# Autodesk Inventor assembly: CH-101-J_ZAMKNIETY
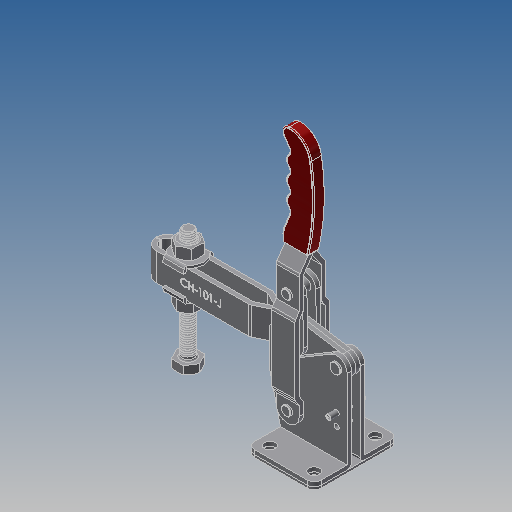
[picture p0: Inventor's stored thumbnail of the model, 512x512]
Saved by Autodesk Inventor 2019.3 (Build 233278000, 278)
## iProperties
Company: Î¢ÈíÖÐ¹ú
Created: 2012-09
Part Number: CH-101-J_ZAMKNIETY
Material: Ogólny
Description: STEP AP203
Document SubType Name: Assembly
Designer: CADENGINEERING4
Sending System: SolidWorks 2010
Preprocessor: SwSTEP 2.0
Title: CH-101-J.STEP
Author: Î¢ÈíÓÃ»§
Revision Number: ÈÎºÎ
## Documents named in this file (16)
- E:\STRONA\Piotrek\CH-101-J\CH-101-J_ZAMKNIETY.iam
- E:\STRONA\Piotrek\CH-101-J\CH-101-J-02 U-BAR.ipt
- E:\STRONA\Piotrek\CH-101-J\CH-101-J-01 FLANGED BASE.ipt
- E:\STRONA\Piotrek\CH-101-J\CH-FW-580.ipt
- E:\STRONA\Piotrek\CH-101-J\CH-101-J-06.ipt
- E:\STRONA\Piotrek\CH-101-J\CH-101-J-03 HANDLE.ipt
- E:\STRONA\Piotrek\CH-101-J\CH-SA-58500 SPINDLE SUPPLIED.ipt
- E:\STRONA\Piotrek\CH-101-J\CH-101-J-11.ipt
- E:\STRONA\Piotrek\CH-101-J\CH-10247-08.ipt
- E:\STRONA\Piotrek\CH-101-J\CH-101-J-07.ipt
- E:\STRONA\Piotrek\CH-101-J\CH-10247-05.ipt
- E:\STRONA\Piotrek\CH-101-J\CH-101-J-05.ipt
- E:\STRONA\Piotrek\CH-101-J\3-8-16 LOCK NUT.ipt
- E:\STRONA\Piotrek\CH-101-J\CH-SA-58500 NUT.ipt
- E:\STRONA\Piotrek\CH-101-J\CH-101-J-04 CONNECTING-PLATE.ipt
- E:\STRONA\Piotrek\CH-101-J\CH-10247-09.ipt
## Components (21 placed, 21 different names)
1. CH-101-J-02 U-BAR_1
2. CH-101-J-01 FLANGED BASE_2
3. CH-FW-580_3
4. CH-101-J-06_4
5. CH-101-J-03 HANDLE_5
6. CH-SA-58500 SPINDLE SUPPLIED_6
7. CH-101-J-11_7
8. CH-10247-08_8
9. CH-101-J-06_9
10. CH-101-J-07_10
11. CH-10247-05_11
12. CH-101-J-05_12
13. 3-8-16 LOCK NUT_13
14. CH-SA-58500 NUT_14
15. 3-8-16 LOCK NUT_15
16. CH-101-J-04 CONNECTING-PLATE_16
17. CH-10247-08_17
18. CH-FW-580_18
19. CH-101-J-11_19
20. CH-10247-09_20
21. CH-SA-58500 NUT_21
